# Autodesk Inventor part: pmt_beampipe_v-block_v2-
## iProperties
Shininess: 64.0
Length Units: 11269
Angle Units: 11279
Time Units: 11290
Mass Units: 11283
Length Display Precision: 3
Angle Display Precision: 2
Compacted: True
Part Number: pmt_beampipe_v-block_v2-
Document SubType Name: Modeling
Created: 2004-08
Designer: John Blackburn
Manufacturer: Standard
Standards Organization: Custom
Material: Aluminum-6061
Density: 0.0
Volumn: 0.0
Area: 0.0
PropertySet Name: Model Information
Control State: 0
Master: False
Checked Out: False
Author: John Blackburn
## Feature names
1. Extrusion1
2. Hole1
3. Hole4
4. Hole5
5. Hole6
